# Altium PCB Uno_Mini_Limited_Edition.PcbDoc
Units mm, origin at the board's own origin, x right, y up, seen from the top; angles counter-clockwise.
Board outline 34.2 x 26.7 mm, 4 copper layers (TOP, SIG 1, PWR, BOTTOM), stack 1.586 mm thick; 63 components, 57 nets, 379 pads, 91 vias.
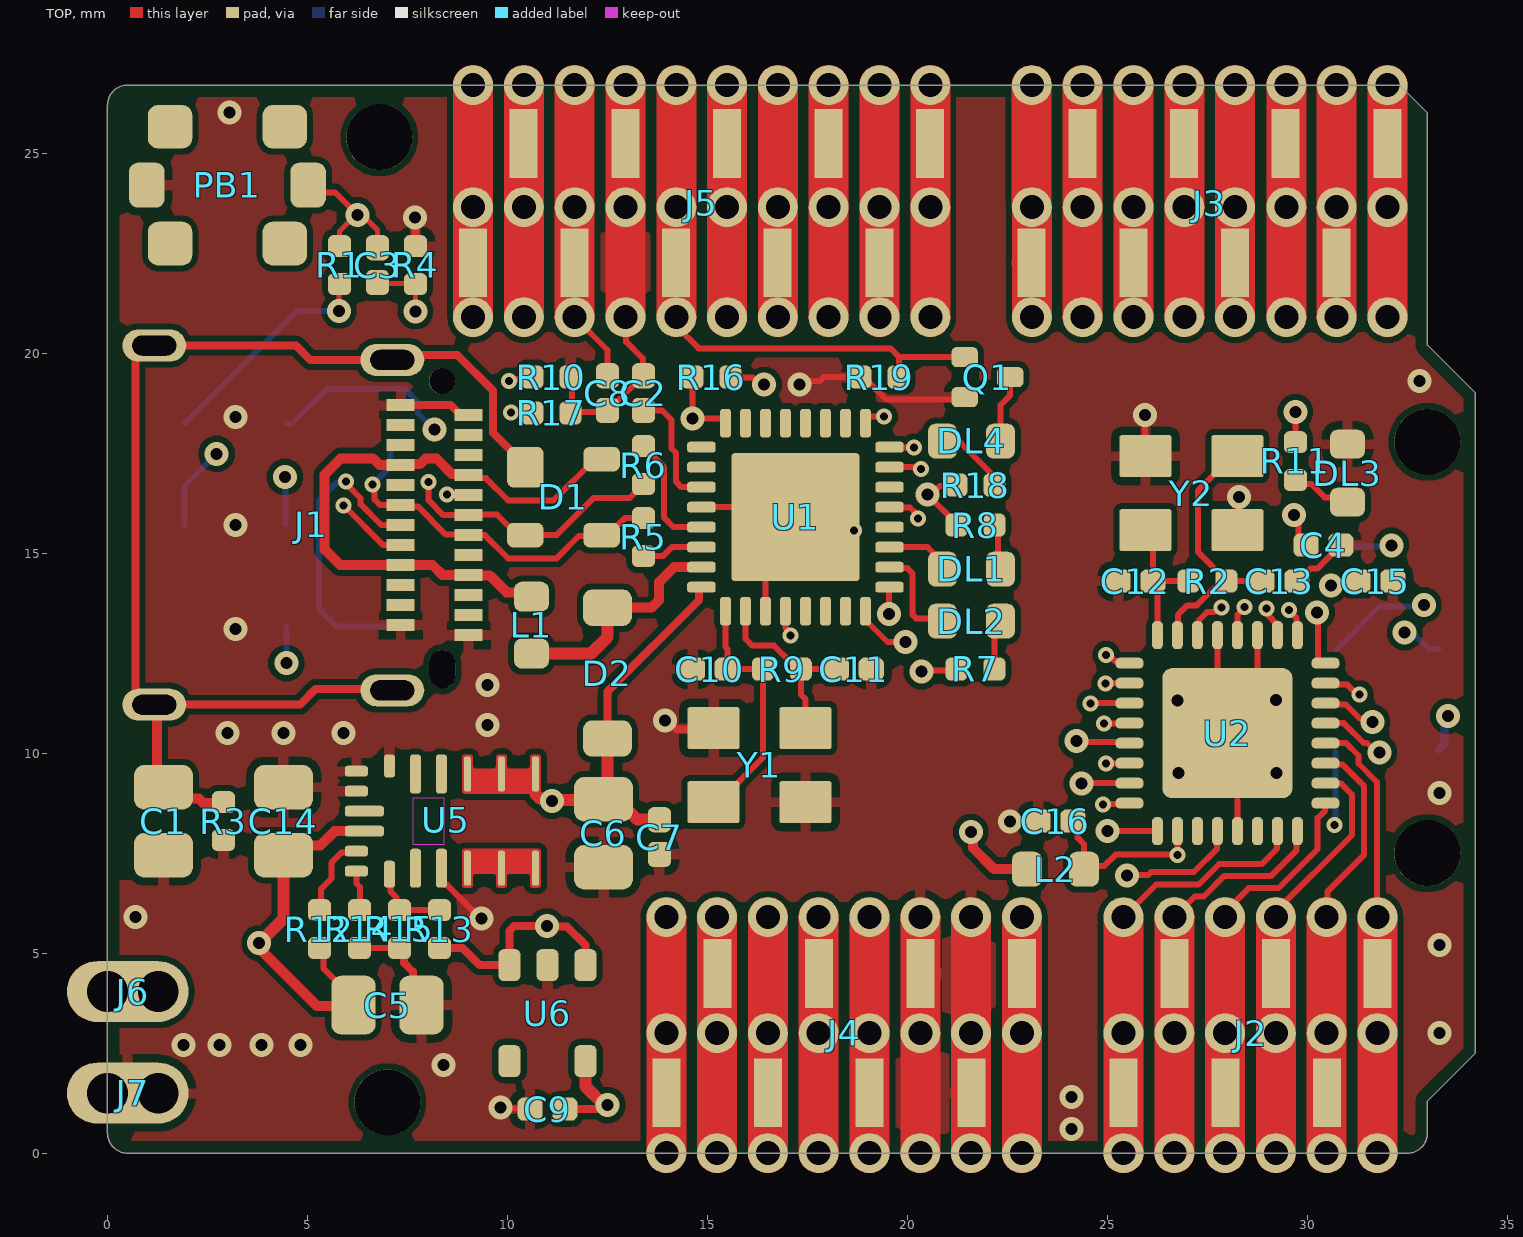
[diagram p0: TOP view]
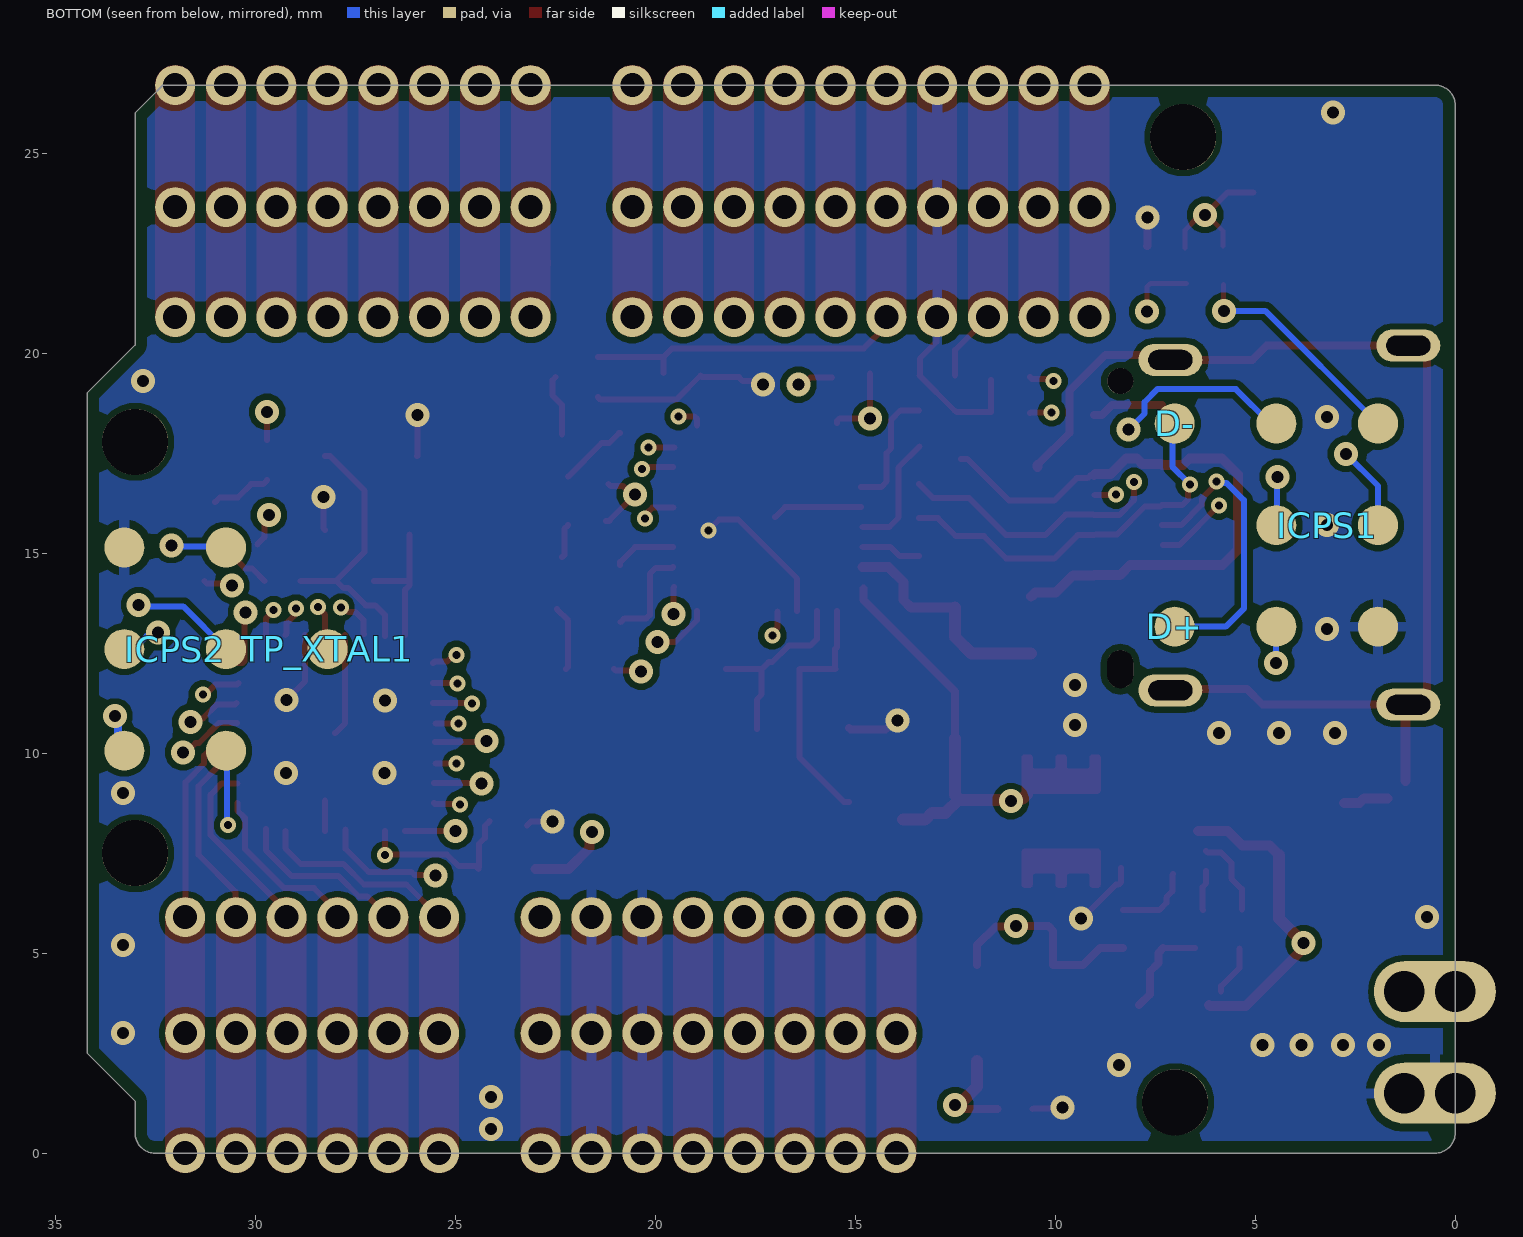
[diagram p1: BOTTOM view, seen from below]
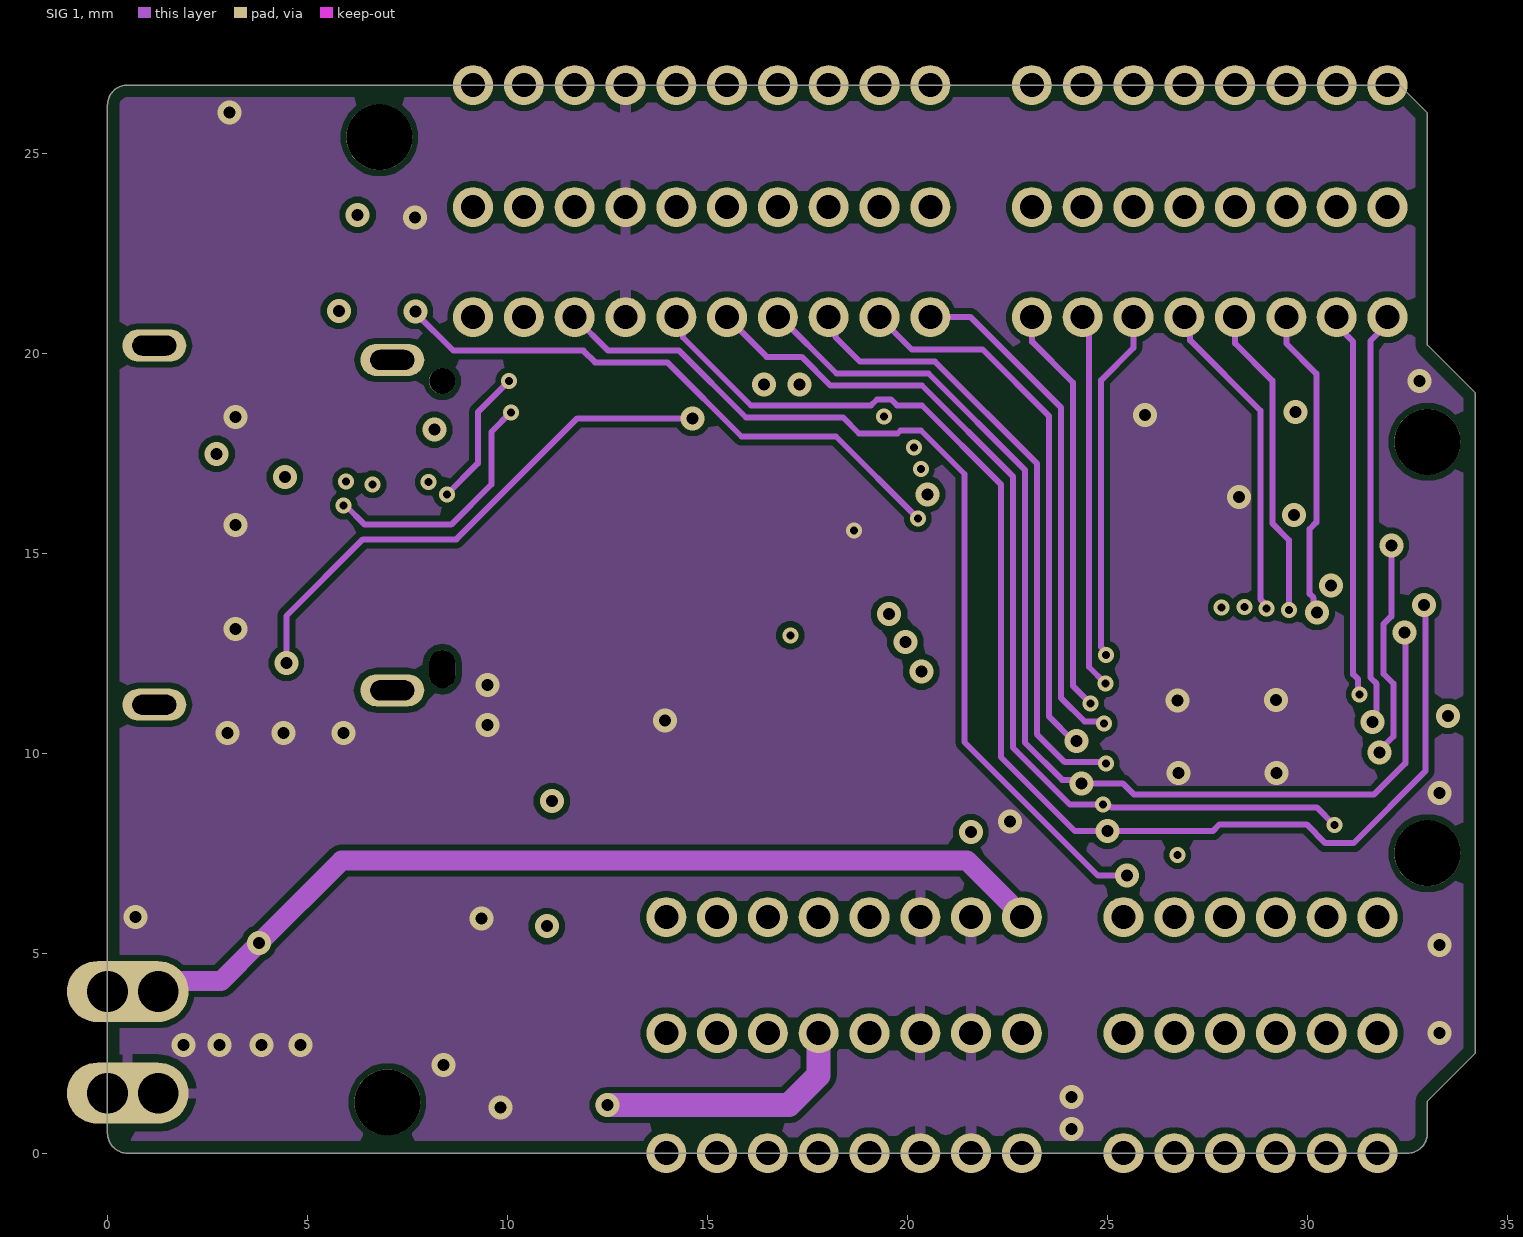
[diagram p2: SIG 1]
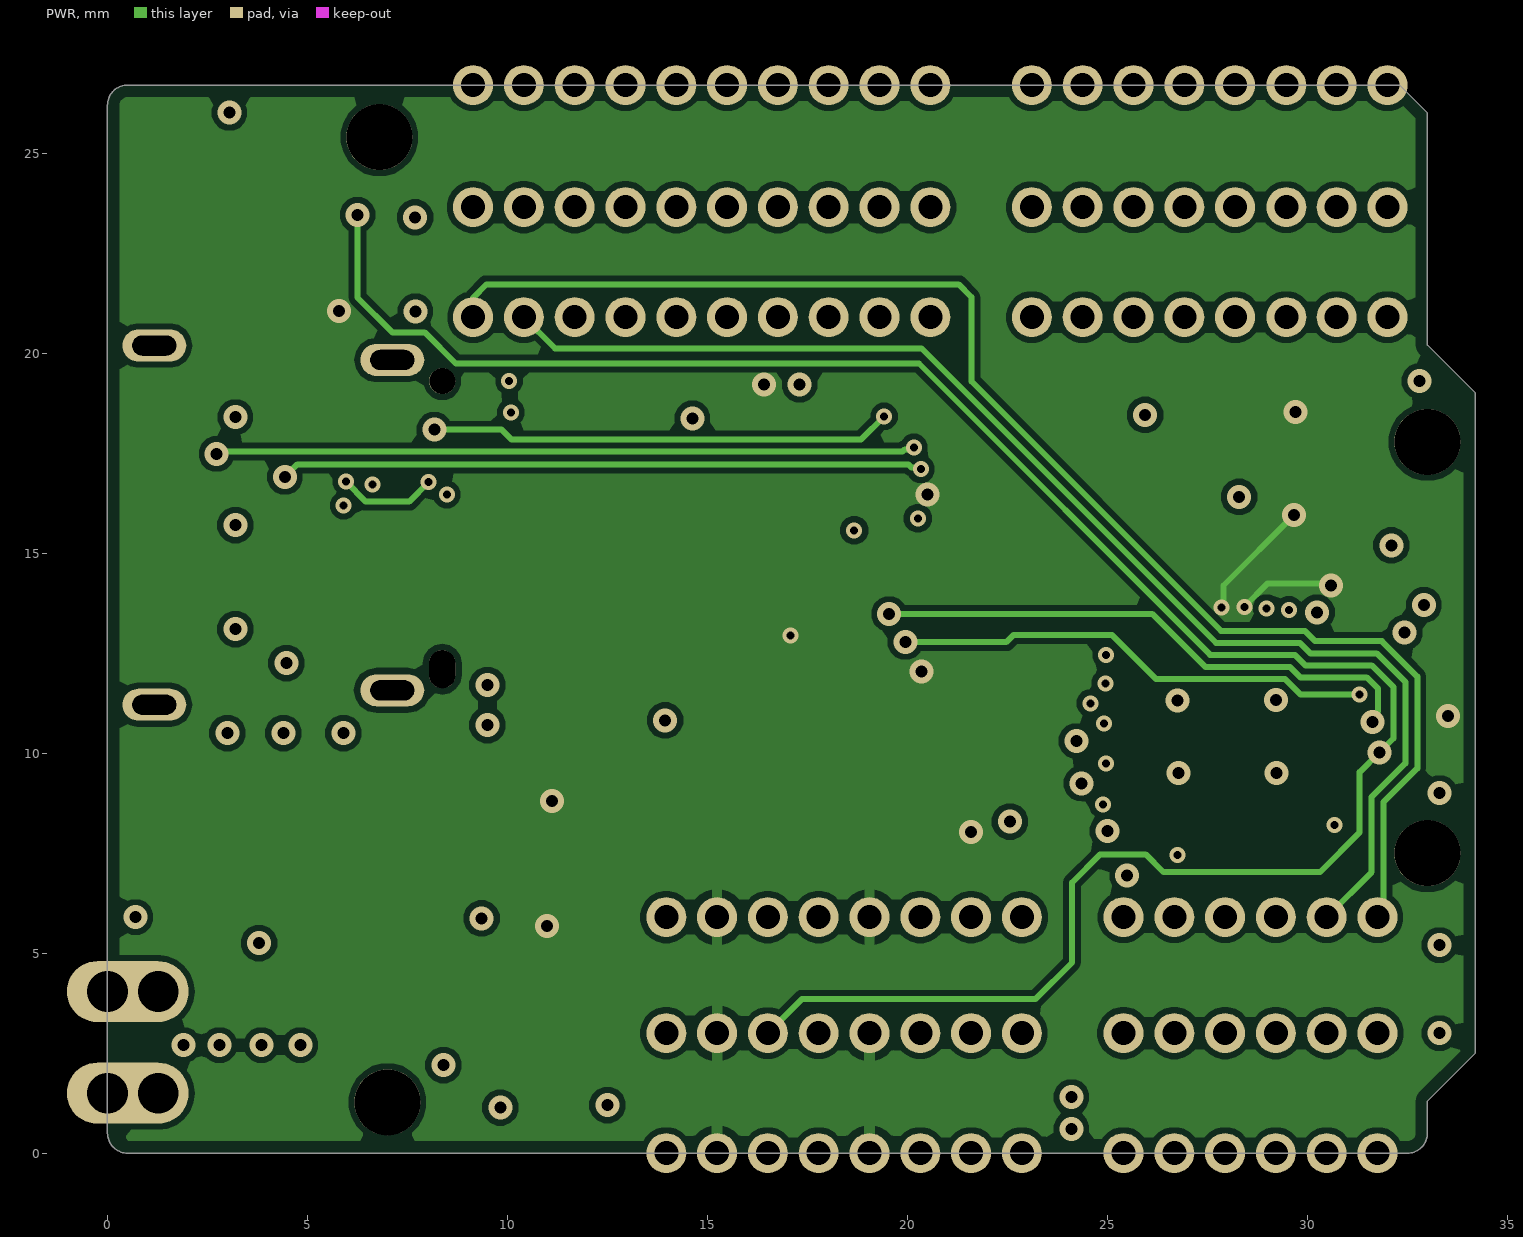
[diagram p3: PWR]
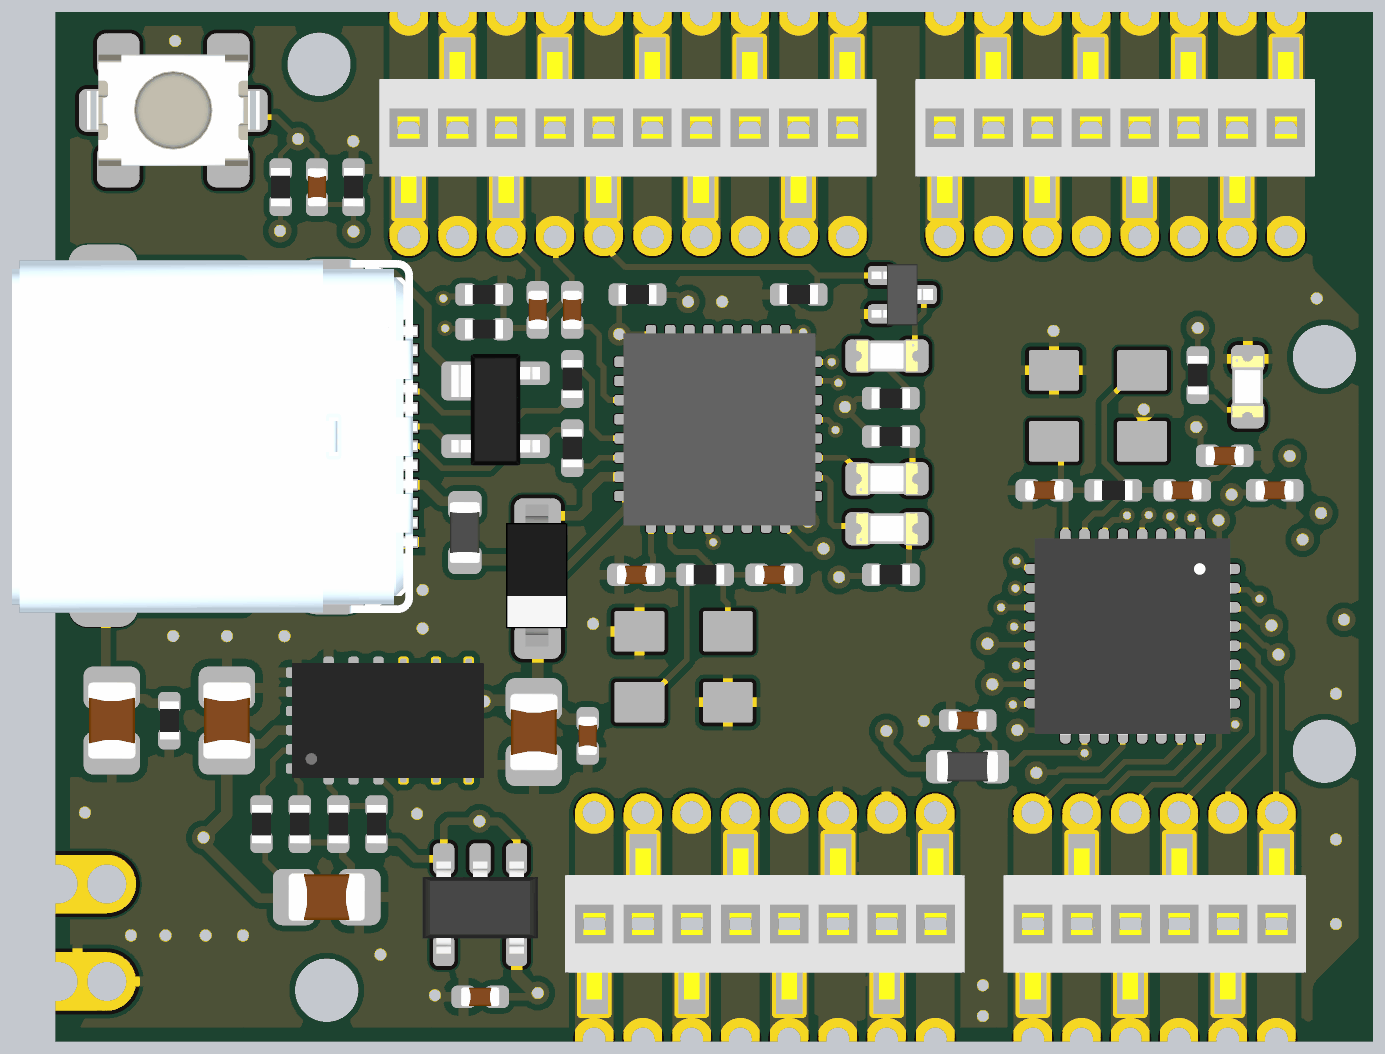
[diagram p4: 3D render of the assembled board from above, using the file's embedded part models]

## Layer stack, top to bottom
Top Solder: solder mask 0.0102, Solder Resist, Dk 3.5
TOP: signal copper 0.018
Dielectric1: prepreg 0.14, PP-014, Dk 4.2
SIG 1: signal copper 0.035
Dielectric2: core 1.2, FR-4, Dk 4.8
PWR: signal copper 0.035
Dielectric3: prepreg 0.14, PP-014, Dk 4.2
BOTTOM: signal copper 0.018
Bottom Solder: solder mask 0.0102, Solder Resist, Dk 3.5

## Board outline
0,0.5 0,26.2 cw(c0.5,26.2) 0.5,26.7 32.3,26.7 33,26 33,20.2 34.2,19 34.2,2.5 33,1.3 33,0.5 cw(c32.5,0.5) 32.5,0 0.5,0 cw(c0.5,0.5)

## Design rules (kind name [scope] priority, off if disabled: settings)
BoardOutlineClearance [All] p1: gap=0.3 ignorepadtopadclearanceinfootprint=FALSE
Clearance [All] p1: gap=0.15 ignorepadtopadclearanceinfootprint=TRUE
ComponentClearance [All] p1: gap=0.254 collisioncheckmode=3 verticalgap=-10 showdistances=FALSE
MinimumSolderMaskSliver [All] p1: minsoldermaskwidth=0.05
PlaneClearance [All] p1: clearance=0.3
PlaneConnect [All] p1: planeconnectstyle=Direct reliefexpansion=0.508 reliefentries=4 reliefconductorwidth=0.254 reliefairgap=0.254
PolygonConnect [All] p1: thpad.connectstyle=Relief thpad.reliefconductorwidth=0.254 thpad.reliefentries=4 thpad.polygonreliefangle="90 Angle" thpad.airgapwidth=0.2 smdpad.connectstyle=Relief smdpad.reliefconductorwidth=0.254 smdpad.reliefentries=4 smdpad.polygonreliefangle="90 Angle" smdpad.airgapwidth=0.2 via.connectstyle=Direct via.reliefconductorwidth=0.254 via.reliefentries=4 via.polygonreliefangle="90 Angle" via.airgapwidth=0.254
RoomDefinition Uno_Mini_LE [InComponentClass('Uno_Mini_LE')] p1: confinementstyle=ConfineIn formatcopy=TRUE lockcomponents=FALSE outline -25.5,-0.864 74.8,-0.864 74.8,44.5 -25.5,44.5
RoutingVias [All] p1: holewidth=0.2 width=0.4 viastyle="Through Hole" minholewidth=0.2 minwidth=0.4 maxholewidth=10 maxwidth=10
SilkToSilkClearance [All] p1: silktosilkclearance=0.05
SilkToSolderMaskClearance [IsPad] p1: minsilkscreentomaskgap=0.05 clearancetoexposedcopper=TRUE
SolderMaskExpansion [All] p1: expansion=0.102 istentingtop=FALSE
Width [All] p1: maxlimit=25.4 minlimit=0.127 preferedwidth=0.127 minimp=50.000000 maximp=50.000000 favimp=50.000000
24 further rules are at their usual default settings.

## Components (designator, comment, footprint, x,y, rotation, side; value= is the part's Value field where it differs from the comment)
C1 "C0805C472KDRACTU" CAP-0805 1.4,8.3 r90 top value=4.7nF
C2 "C0402C105K8PACTU" CAP-0402 13.4,19 r270 top value=1µF
C3 "C0402C104K4RACTU" CAP-0402 6.75,22.2 r90 top value=100nF
C4 "C0402C104K4RACTU" CAP-0402 30.4,15.2 r180 top value=100nF
C5 "GRM219R61C226ME15K" CAP-0805 7,3.7 r180 top value=22µF
C6 "GRM219R61C226ME15K" CAP-0805 12.4,8 r90 top value=22µF
C7 "C0402C104K4RACTU" CAP-0402 13.8,7.9 r90 top value=100nF
C8 "C0402C104K4RACTU" CAP-0402 12.5,19 r270 top value=100nF
C9 "C0402C105K8PACTU" CAP-0402 11,1.1 r0 top value=1µF
C10 "C0402H100J5GACTU" CAP-0402 15.06,12.1 r0 top value=10pF
C11 "C0402H100J5GACTU" CAP-0402 18.66,12.1 r180 top value=10pF
C12 "C0402H100J5GACTU" CAP-0402 25.7,14.3 r0 top value=10pF
C13 "C0402H100J5GACTU" CAP-0402 29.3,14.3 r180 top value=10pF
C14 "GRM219R61C226ME15K" CAP-0805 4.4,8.3 r270 top value=22µF
C15 "C0402C104K4RACTU" CAP-0402 31.7,14.3 r180 top value=100nF
C16 "C0402C104K4RACTU" CAP-0402 23.7,8.3 r0 top value=100nF
D1 "PRTR5V0U2X,215" SOT190P230X110-4N 11.4,16.4 r270 top
D2 "PMEG6020AELRX" SOD123-1 12.5,12 r90 top
D+ "CMP-018-0005-A.3" TP-1.00MM#1 7.2,13.64 r90 bottom
D- "CMP-018-0005-A.3" TP-1.00MM#2 7.01,17.74 r90 bottom
DL1 "KPT-1608SECK" LEDC1608X80N-AK 21.6,14.6 r0 top
DL2 "KPT-1608SECK" LEDC1608X80N-AK 21.6,13.3 r0 top
DL3 "HSMG-C190" LEDC1608X80N-AK 31,17 r270 top locked
DL4 "KPT-1608SECK" LEDC1608X80N-AK 21.6,17.8 r180 top
ICPS1 "PINHD-2X03-SM-TP" 2X03-TP 3.2,15.7 r270 bottom
ICPS2 "PINHD-2X03-SM-TP" 2X03-TP 32,12.6 r90 bottom locked
J1 "12401598E4#2A" 12401598E4#2A 5.1,15.7 r270 top locked
J2 "RMS-106-02-L-S" RMS-106-02-L-S-Footprint-1 28.58,3 r180 top
J3 "RSM-108-02-L-S" RMS-108-02-L-S-Footprint-1 27.55,23.75 r180 top
J4 "RSM-108-02-L-S" RMS-108-02-L-S-Footprint-1 18.42,3 r180 top
J5 "RSM-110-02-L-S" RMS-110-02-L-S-Footprint-1 14.85,23.75 r180 top
J6 "HEADER_2.54mm_CASTELLATED_1x1" PINHD-1X14_5VF 1.27,4.04 r90 top locked
J7 "HEADER_2.54mm_CASTELLATED_1x1" PINHD-1X14_5VF 1.27,1.5 r90 top locked
L1 "BLM18PG471SN1D" L-0603 10.6,13.2 r270 top
L2 "BLM18PG471SN1D" L-0603 23.7,7.1 r0 top
PB1 "PTS820J25KSMTRLFS" C&K_PTS820_NO_HOLES-1 3,24.2 r0 top locked
Q1 "2N7002T-7-F" SOT523 22,19.4 r270 top
R1 "CRCW040210K0FKED" RES-0402 5.8,22.2 r270 top value=10k
R2 "CRCW04021M00FKED" RES-0402 27.5,14.3 r180 top value=1M
R3 "CRCW04021M00FKED" RES-0402 2.9,8.3 r90 top value=1M
R4 "CRCW04021K00FKEDC" RES-0402 7.7,22.2 r90 top value=1k
R5 "CRCW040222R0JNEDC" RES-0402 13.4,15.4 r270 top value=22
R6 "CRCW040222R0JNEDC" RES-0402 13.4,17.2 r90 top value=22
R7 "CRCW0402330RJNED" RES-0402 21.7,12.1 r180 top value=330
R8 "CRCW0402330RJNED" RES-0402 21.7,15.7 r0 top value=330
R9 "CRCW04021M00FKED" RES-0402 16.86,12.1 r0 top value=1M
R10 "RC0402FR-075K1L" RES-0402 11.1,19.4 r180 top
R11 "CRCW0402330RJNED" RES-0402 29.7,17.3 r90 top value=330
R12 "CRCW0402100KFKEDC" RES-0402 5.3,5.6 r270 top value=100k
R13 "CRCW0402100KFKEDC" RES-0402 8.3,5.6 r270 top value=100k
R14 "CRCW040239K0FKED" RES-0402 6.3,5.6 r90 top value=39k
R15 "CRCW040219K1FKEDC" RES-0402 7.3,5.6 r90 top value=19.1k
R16 "CRCW040210K0FKED" RES-0402 15.1,19.4 r0 top locked value=10k
R17 "RC0402FR-075K1L" RES-0402 11.1,18.5 r0 top
R18 "CRCW0402330RJNED" RES-0402 21.7,16.7 r0 top value=330
R19 "CRCW04021M00FKED" RES-0402 19.3,19.4 r0 top value=1M
TP_XTAL1 "CMP-018-0005-A.3" TP-1.00MM#3 27.7,12.7 r90 bottom
U1 "ATMEGA16U2" ATMEL_QFN32 17.2,15.9 r90 top locked
U2 "ATMEGA328P-MUR" ATMEGA328P-MUR-Footprint-1 28,10.5 r270 top locked
U5 "MPM3610AGQV-P" POWER-LQFN20 8.6,8.3 r90 top
U6 "AP2112K-3.3TRG1" SOT25 11,3.5 r180 top
Y1 "CX3225SB16000D0GZJC1" CX3225SB16000D0GZJC1 16.3,9.7 r0 top
Y2 "CX3225SB16000D0GZJC1" CX3225SB16000D0GZJC1 27.1,16.5 r180 top

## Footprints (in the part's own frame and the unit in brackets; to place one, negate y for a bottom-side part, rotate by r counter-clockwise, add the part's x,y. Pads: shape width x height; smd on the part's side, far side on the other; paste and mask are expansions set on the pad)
2X03-TP [mm]
  rrect100% 1x1 smd paste+0: 1(-2.54,-1.27) 2(-2.54,1.27) 3(0,-1.27) 4(0,1.27) 5(2.54,-1.27) 6(2.54,1.27)
12401598E4#2A [mm]
  oval 1x1.8 on Top Paste: 0(-4.499,-3.932) 0(-4.131,2.023) 0(4.131,2.026) 0(4.461,-3.925)
  round 0.65 hole 0.65 unplated mask+0.05: 0(-3.6,3.27)
  oval 0.95x0.65 hole 0.65 slot 0.95 at 0 deg unplated mask+0: 0(3.6,3.27)
  rect 0.3x0.7 smd mask+0.04: A1(-2.75,3.93) A2(-2.25,3.93) A3(-1.75,3.93) A4(-1.25,3.93) A5(-0.75,3.93) A6(-0.25,3.93) A7(0.25,3.93) A8(0.75,3.93) A9(1.25,3.93) A10(1.75,3.93) B1(2.5,2.23) B2(2,2.23) B3(1.5,2.23) B4(1,2.23) B5(0.5,2.23) B6(0,2.23) B7(-0.5,2.23) B8(-1,2.23) B9(-1.5,2.23) B10(-2,2.23) B11(-2.5,2.23) B12(-3,2.23)
  rect 0.3x0.7 smd mask+0.03: A11(2.25,3.93) A12(2.75,3.93)
  oval 0.8x1.6 hole 0.5 slot 1.1 at 90 deg: "SHIELD 1"(-4.13,2.02) "SHIELD 2"(4.13,2.02) "SHIELD 3"(-4.49,-3.93) "SHIELD 4"(4.49,-3.93)
  body extent -4.6,-6.3 4.6,4.25, height 3.3
ATMEGA328P-MUR-Footprint-1 [mm]
  rrect80% 0.7x0.27 smd mask+0.03: 1(-2.45,1.75) 2(-2.45,1.25) 3(-2.45,0.75) 4(-2.45,0.25) 5(-2.45,-0.25) 6(-2.45,-0.75) 7(-2.45,-1.25) 8(-2.45,-1.75) 17(2.45,-1.75) 18(2.45,-1.25) 19(2.45,-0.75) 20(2.45,-0.25) 21(2.45,0.25) 22(2.45,0.75) 23(2.45,1.25) 24(2.45,1.75)
  rrect80% 0.27x0.7 smd mask+0.03: 9(-1.75,-2.45) 10(-1.25,-2.45) 11(-0.75,-2.45) 12(-0.25,-2.45) 13(0.25,-2.45) 14(0.75,-2.45) 15(1.25,-2.45) 16(1.75,-2.45) 25(1.75,2.45) 26(1.25,2.45) 27(0.75,2.45) 28(0.25,2.45) 29(-0.25,2.45) 30(-0.75,2.45) 31(-1.25,2.45) 32(-1.75,2.45)
  rrect15% 3.254x3.254 smd paste-5 mask+0.05: 33(0,0)
  body extent -2.56,-2.56 2.56,2.56, height 1.01
ATMEL_QFN32 [mm]
  rrect50% 0.711x0.27 smd mask+0.03: 1(-2.351,1.75) 2(-2.351,1.25) 3(-2.351,0.75) 4(-2.351,0.25) 5(-2.351,-0.25) 6(-2.351,-0.75) 7(-2.351,-1.25) 8(-2.351,-1.75) 17(2.351,-1.75) 18(2.351,-1.25) 19(2.351,-0.75) 20(2.351,-0.25) 21(2.351,0.25) 22(2.351,0.75) 23(2.351,1.25) 24(2.351,1.75)
  rrect50% 0.27x0.711 smd mask+0.03: 9(-1.75,-2.351) 10(-1.25,-2.351) 11(-0.75,-2.351) 12(-0.25,-2.351) 13(0.25,-2.351) 14(0.75,-2.351) 15(1.25,-2.351) 16(1.75,-2.351) 25(1.75,2.351) 26(1.25,2.351) 27(0.75,2.351) 28(0.25,2.351) 29(-0.25,2.351) 30(-0.75,2.351) 31(-1.25,2.351) 32(-1.75,2.351)
  rrect5% 3.2x3.2 smd paste-3.302 mask+0.05: EXP(0,0)
  body extent -2.51,-2.54 2.49,2.46, height 0.85
C&K_PTS820_NO_HOLES-1 [mm]
  rrect49% 0.89x1.12 smd: 5(-2.015,0) 6(2.015,0)
  rrect46% 1.11x1.09 smd: PAD(-1.434,-1.46) PAD(-1.434,1.46) PAD(1.434,-1.46) PAD(1.434,1.46)
  body extent -2.25,-1.45 2.25,1.45, height 2
CAP-0402 [mm] "Chip Capacitor, 2-Leads, Body  0402 (in) 1005 (mm), IPC Medium Density"
  rrect52% 0.63x0.58 smd mask+0: 1(-0.435,0) 2(0.435,0)
  body extent -0.5,-0.25 0.5,0.25, height 0.5
CAP-0805 [mm] "Chip Capacitor, Body 0805 imperial, 2.0x1.2mm, IPC Medium Density"
  rrect45% 1.11x1.47 smd mask+0: 1(-0.85,0) 2(0.85,0)
  body extent -1,-0.62 1,0.63, height 1.25
CX3225SB16000D0GZJC1 [mm]
  rrect10% 1.3x1.05 smd: 1(-1.15,-0.925) 2(1.15,-0.925) 3(1.15,0.925) 4(-1.15,0.925)
  body extent -1.59,-1.21 1.59,1.21, height 0.6
L-0603 [mm] "Chip Inductor - Body 0603 imperial,1.6x0.8mm, IPC High Density"
  rrect51% 0.75x0.87 smd mask+0: 1(-0.71,0) 2(0.71,0)
  body extent -0.8,-0.4 0.8,0.4, height 0.8
LEDC1608X80N-AK [mm]
  rrect50% 0.72x0.87 smd: A(0.725,0) C(-0.725,0)
  body extent -0.8,-0.4 0.8,0.4, height 0.79
PINHD-1X14_5VF [mil]
  round 27.56 hole 40 mask+7.87: 1(0,50)
  oval 60x120 hole 40 copper offset 0,30 paste-100: 1(0,0)
POWER-LQFN20 [mm]
  rrect52% 0.675x0.27 smd paste+0 mask+0: 1(-1.328,1.55)
  rrect52% 0.975x0.27 smd paste+0 mask+0: 2(-1.178,0.9) 3(-1.178,0.25) 10(1.178,0.25) 11(1.178,0.9)
  rrect52% 0.875x0.17 smd paste+0 mask+0: 4(-1.178,-0.4) 5(-1.178,-1.25) 6(-1.178,-2.1) 7(1.178,-2.1) 8(1.178,-1.25) 9(1.178,-0.4)
  rrect52% 0.575x0.27 smd paste+0 mask+0: 12(1.378,1.55)
  rrect52% 0.27x0.575 smd paste+0 mask+0: 13(1.25,2.378) 14(0.75,2.378) 17(-0.75,2.378) 18(-1.25,2.378)
  rrect52% 0.27x0.975 smd paste+0 mask+0: 15(0.25,2.178) 16(-0.25,2.178)
  TOP region: 0.69,-2.165 0.695,-2.192 0.711,-2.214 0.733,-2.23 0.76,-2.235 0.76,-2.235 1.595,-2.235 1.622,-2.23 1.644,-2.214 1.66,-2.192 1.665,-2.165 1.665,-2.165 1.665,-2.035 1.66,-2.008 1.644,-1.986 1.622,-1.97 1.595,-1.965 1.595,-1.965 1.38,-1.965 1.353,-1.96 1.331,-1.944 1.315,-1.922 1.31,-1.895 1.31,-1.895 1.31,-1.455 1.31,-1.455 1.315,-1.428 1.33,-1.406 1.353,-1.39 1.38,-1.385 1.38,-1.385 1.595,-1.385 1.622,-1.38 1.644,-1.364 1.66,-1.342 1.665,-1.315 1.665,-1.315 1.665,-1.185 1.665,-1.185 1.66,-1.158 1.645,-1.136 1.622,-1.12 1.595,-1.115 1.595,-1.115 1.38,-1.115 1.353,-1.11 1.331,-1.094 1.315,-1.072 1.31,-1.045 1.31,-1.045 1.31,-1.045 1.31,-0.605 1.315,-0.578 1.331,-0.556 1.353,-0.54 1.38,-0.535 1.38,-0.535 1.595,-0.535 1.595,-0.535 1.622,-0.53 1.645,-0.514 1.66,-0.492 1.665,-0.465 1.665,-0.465 1.665,-0.465 1.665,-0.335 1.66,-0.308 1.644,-0.286 1.622,-0.27 1.595,-0.265 1.595,-0.265 0.76,-0.265 0.733,-0.27 0.711,-0.286 0.695,-0.308 0.69,-0.335 0.69,-0.335
  TOP region: -1.665,-2.165 -1.66,-2.192 -1.644,-2.214 -1.622,-2.23 -1.595,-2.235 -1.595,-2.235 -0.76,-2.235 -0.733,-2.23 -0.711,-2.214 -0.695,-2.192 -0.69,-2.165 -0.69,-2.165 -0.69,-2.165 -0.69,-0.335 -0.695,-0.308 -0.711,-0.286 -0.733,-0.27 -0.76,-0.265 -0.76,-0.265 -1.595,-0.265 -1.622,-0.27 -1.645,-0.286 -1.66,-0.308 -1.665,-0.335 -1.665,-0.335 -1.665,-0.335 -1.665,-0.465 -1.66,-0.492 -1.644,-0.514 -1.622,-0.53 -1.595,-0.535 -1.595,-0.535 -1.38,-0.535 -1.353,-0.54 -1.331,-0.556 -1.315,-0.578 -1.31,-0.605 -1.31,-0.605 -1.31,-1.045 -1.31,-1.045 -1.315,-1.072 -1.33,-1.094 -1.353,-1.11 -1.38,-1.115 -1.38,-1.115 -1.595,-1.115 -1.622,-1.12 -1.644,-1.136 -1.66,-1.158 -1.665,-1.185 -1.665,-1.185 -1.665,-1.315 -1.665,-1.315 -1.66,-1.342 -1.645,-1.364 -1.622,-1.38 -1.595,-1.385 -1.595,-1.385 -1.38,-1.385 -1.353,-1.39 -1.331,-1.406 -1.315,-1.428 -1.31,-1.455 -1.31,-1.455 -1.31,-1.455 -1.31,-1.895 -1.31,-1.895 -1.315,-1.922 -1.331,-1.944 -1.353,-1.96 -1.38,-1.965 -1.38,-1.965 -1.595,-1.965 -1.595,-1.965 -1.622,-1.97 -1.644,-1.985 -1.66,-2.008 -1.665,-2.035 -1.665,-2.035
  TOP keep-out region: -0.575,0.18 0.575,0.18 0.575,0.97 -0.575,0.97
  body extent -1.5,-2.5 1.5,2.5, height 1.6
RES-0402 [mm] "Chip Resistor, 2-Leads, Body  0402 (in) 1005 (mm), IPC Medium Density"
  rrect51% 0.55x0.58 smd mask+0: 1(-0.475,0) 2(0.475,0)
  body extent -0.5,-0.25 0.5,0.25, height 0.34
RMS-106-02-L-S-Footprint-1 [mm]
  rect 0.7x1.715 smd: 1(-3.175,-1.492) 2(-1.905,1.492) 3(-0.635,-1.492) 4(0.635,1.492) 5(1.905,-1.492) 6(3.175,1.492)
  body extent -3.94,-1.97 3.94,1.97, height 6.09
RMS-108-02-L-S-Footprint-1 [mm]
  rect 0.7x1.715 smd: 1(-4.445,-1.492) 2(-3.175,1.492) 3(-1.905,-1.492) 4(-0.635,1.492) 5(0.635,-1.492) 6(1.905,1.492) 7(3.175,-1.492) 8(4.445,1.492)
  body extent -5.21,-1.97 5.21,1.97, height 6.02
RMS-110-02-L-S-Footprint-1 [mm]
  rect 0.7x1.715 smd: 1(-5.715,-1.492) 2(-4.445,1.492) 3(-3.175,-1.492) 4(-1.905,1.492) 5(-0.635,-1.492) 6(0.635,1.492) 7(1.905,-1.492) 8(3.175,1.492) 10(5.715,1.492)
  rect 0.7x1.715 smd mask+0.12: 9(4.445,-1.492)
  body extent -6.48,-1.97 6.48,1.97, height 6.11
SOD123-1 [mm]
  rrect50% 0.91x1.22 smd: A(1.635,0) C(-1.635,0)
  body extent -1.78,-0.78 1.92,0.82, height 1.27
SOT25 [mil]
  rrect50% 21.65x31.5 smd: 1(-37.4,-47.24) 2(0,-47.24) 3(37.4,-47.24) 4(37.4,47.24) 5(-37.4,47.24)
  body extent -59,-44 59,50, height 43
SOT190P230X110-4N [mm]
  rrect33% 1.01x0.91 smd paste+0 mask+0: 1(-0.75,-0.955)
  rrect49% 0.61x0.91 smd paste+0 mask+0: 2(0.95,-0.955) 3(0.95,0.955) 4(-0.95,0.955)
  body extent -1.45,-1.15 1.45,1.15, height 1
SOT523 [mm]
  rrect50% 0.5x0.66 smd: D(0,0.57) G(-0.5,-0.57) S(0.5,-0.57)
  body extent -0.8,-0.8 0.8,0.8, height 0.8
TP-1.00MM#1 [mm]
  rrect100% 1x1 smd paste-2.54: X(-0.48,-0.19)
TP-1.00MM#2 [mm]
  rrect100% 1x1 smd paste-2.54: X(0.5,0)
TP-1.00MM#3 [mm]
  rrect100% 1x1 smd paste-2.54: X(-0.1,0.49)

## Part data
C1: library part C0059-A.9, "CAP CHIP 0805 4.7nF 1000V X7R 10%", Case Code (Imperial)=0805, Case Code (Metric)=2012, Dielectric=X7R, Manufacturer=KEMET, Tolerance=10%, Voltage=1kV
C2 C9: library part C0017-A.9, "CAP CHIP 0402 1uF 10V X5R 10%", Case Code (Imperial)=0402, Case Code (Metric)=1005, Dielectric=X5R, Manufacturer=KEMET, Manufacturer 2=AVX, Manufacturer Part Number 2=GRM155R61A105KE15D, Tolerance=10%, Voltage=10V
C3 C4 C7 C8 C15 C16: library part C0012-A.9, "CAP CHIP 0402 100nF 16V X7R 10%", Case Code (Imperial)=0402, Case Code (Metric)=1005, Dielectric=X7R, Manufacturer=KEMET, Manufacturer 2=AVX, Manufacturer Part Number 2=0402YC104KAT2A, Tolerance=10%, Voltage=16V
C5 C6 C14: library part C0058-A.9, "CAP CHIP 0805 22uF 16V X5R 20%", Case Code (Imperial)=0805, Case Code (Metric)=2012, Dielectric=X5R, Manufacturer=Murata, Manufacturer 2=Samsung, Manufacturer Part Number 2=CL21A226MAQNNNE, Tolerance=20%, Voltage=16V
C10 C11 C12 C13: library part C0006-A.9, "CAP CHIP 0402 10pF 50V C0G 5%", Case Code (Imperial)=0402, Case Code (Metric)=1005, Dielectric=C0G, Manufacturer=KEMET, Manufacturer 2=AVX, Manufacturer Part Number 2=04025A100KAT2A, Tolerance=5%, Voltage=50V
D1: library part D0025-A.3, "TVS ARRAY 4LIN.8kV 1pF SOT143B", Manufacturer=Nexperia
D2: library part D0026-A.2, "DIODE SCHOTTKY SMD 1A 40V SOD123FL", Manufacturer=Nexperia
D+ D- TP_XTAL1: library part UT0013-A.2, "Test point 1.00mm"
DL1 DL2 DL4: library part L0006-A.4, "LED SMD 0603 ORANGE601 250mcd 120^", Manufacturer=Kingbright
DL3: library part L0009-A.4, "LED SMD 0603 GREEN/568 15mcd 120^", Manufacturer=Broadcom
ICPS1 ICPS2: library part J0066-A.3, "2X03 6 TEST POINTS"
J1: library part J0220-A.5, "CONN RCP USB3.1 TYPEC 24P SMD RA", Flammability Rating="UL94 V-0", Manufacturer="Amphenol ICC (Commercial Products)"
J2: library part J0193-A.5, "CONN PIN HEADER FEMALE SMD 1X6", Manufacturer=SAMTEC
J3 J4: library part J0194-A.7, "CONN PIN HEADER FEMALE SMD 1X8", Contact Resistance=10mR, Insulation Color=Black, Manufacturer=SAMTEC, Max Operating Temperature=125°C, Min Operating Temperature=-55°C
J5: library part J0196-A.5, "CONN PIN HEADER FEMALE SMD 1X10", Manufacturer=SAMTEC
J6 J7: library part J0207-A.4, "CONN THD HEADER 2.54mm CASTELLATED 1x1"
L1 L2: library part I0006-A.3, "FERRITE SMD 0603 470R 1A 0.2R", Case Code (Imperial)=0603, Case Code (Metric)=1608, Current=1A, DC Resistance (DCR)=200mR, Manufacturer=Murata, Max Operating Temperature=125°C, Min Operating Temperature=-55°C, Package Quantity=1, Test Frequency=100MHz, Tolerance=25%
PB1: library part B0006-A.7, "PUSHBUTTON SMD PTS820 NO HOLES", Color=Black, Manufacturer=C&K, Max Operating Temperature=85°C, Min Operating Temperature=-40°C
Q1: library part T0003-A.2, "MOSFET N-CH 60V 115mA SOT523", Manufacturer="Diodes Inc."
R1 R16: library part R0003-A.5, "RES CHIP 0402 10K 1% 1/16W", Case Code (Imperial)=0402, Case Code (Metric)=1005, Manufacturer=Vishay, Manufacturer 2=Panasonic, Manufacturer Part Number 2=ERJ-2RKF1002X, Power=63mW, Tolerance=1%
R2 R3 R9 R19: library part R0058-A.5, "RES CHIP 0402 1M 1% 1/16W", Case Code (Imperial)=0402, Case Code (Metric)=1005, Manufacturer=Vishay, Manufacturer 2=Panasonic, Manufacturer Part Number 2=ERJ-2RKF1004X, Power=63mW, Tolerance=1%
R4: library part R0007-A.5, "RES CHIP 0402 1K 1% 1/16W", Case Code (Imperial)=0402, Case Code (Metric)=1005, Manufacturer=Vishay, Manufacturer 2=Panasonic, Manufacturer Part Number 2=ERJ-2RKF1001X, Power=63mW, Tolerance=1%
R5 R6: library part R0010-A.5, "RES CHIP 0402 22R 5% 1/16W", Case Code (Imperial)=0402, Case Code (Metric)=1005, Manufacturer=Vishay, Manufacturer 2=Panasonic, Manufacturer Part Number 2=ERJ-2GEJ220X, Power=63mW, Tolerance=5%
R7 R8 R11 R18: library part R0017-A.5, "RES CHIP 0402 330R 5% 1/16W", Case Code (Imperial)=0402, Case Code (Metric)=1005, Manufacturer=Vishay, Manufacturer 2=Panasonic, Manufacturer Part Number 2=ERJ-2GEJ331X, Power=63mW, Tolerance=5%
R10 R17: library part R0210-A.6, "RES CHIP 0402 5K1 1% 1/16W", Case/Package=0402, Manufacturer=YAGEO, Tolerance=1%
R12 R13: library part R0001-A.5, "RES CHIP 0402 100K 1% 1/16W", Case Code (Imperial)=0402, Case Code (Metric)=1005, Manufacturer=Vishay, Manufacturer 2=Panasonic, Manufacturer Part Number 2=ERJ-2RKF1003X, Power=63mW, Tolerance=1%
R14: library part R0036-A.7, "RES CHIP 0402 39K 1% 1/16W", Case Code (Imperial)=0402, Case Code (Metric)=1005, Manufacturer=Vishay, Manufacturer 2=Panasonic, Manufacturer Part Number 2=ERJ-2RKF3902X, Power=63mW, Tolerance=1%
R15: library part R0033-A.5, "RES CHIP 0402 19k1 1% 1/16W", Case Code (Imperial)=0402, Case Code (Metric)=1005, Manufacturer=Vishay, Manufacturer 2=Panasonic, Manufacturer Part Number 2=ERJ-2RKF1912X, Power=63mW, Tolerance=1%
U1: library part U0035-A.7, "IC ATMEGA16U2", Manufacturer=Microchip
U2: library part U0037-A.7, "IC MICROCONTROLLER 8 bit", Case/Package=VQFN, Frequency=20MHz, Manufacturer=Microchip, Max Operating Temperature=125°C, Min Operating Temperature=-40°C
U5: library part U0075-A.8, "IC StpDwn-CONV.21V 1.2A", Case/Package=QFN, Manufacturer=MPS, Max Input Voltage=21V, Max Operating Temperature=125°C, Max Output Current=1.2A, Min Input Voltage=4.5V, Min Operating Temperature=-40°C, Operating Supply Current=200uA, Output Voltage=5.5V, Package Quantity=500, Switching Frequency=2MHz, Voltage - Output 1=18.48V
U6: library part U0027-A.6, "IC V-REG LDO 3V3 600mA +En  SOT25", Manufacturer="Diodes Inc"
Y1 Y2: library part X0019-A.4, "CRYSTAL 16.0000MHZ 8PF SMD", Manufacturer="Kyocera International Inc. Electronic Components"

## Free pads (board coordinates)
  round 1.651 hole 1.651 unplated mask+0: 0(6.8,25.4) 0(7,1.27) 0(33,7.5) 0(33,17.78)
  round 1 hole 0.6 mask+0.05: 2(9.14,20.9) 2(9.14,23.65) 2(9.14,26.7) 2(10.41,20.9) 2(10.41,23.65) 2(10.41,26.7) 2(11.68,20.9) 2(11.68,23.65) 2(11.68,26.7) 2(12.95,20.9) 2(12.95,23.65) 2(12.95,26.7) 2(13.97,0) 2(13.97,3) 2(13.97,5.9) 2(14.22,20.9) 2(14.22,23.65) 2(14.22,26.7) 2(15.24,0) 2(15.24,3) 2(15.24,5.9) 2(15.49,20.9) 2(15.49,23.65) 2(15.49,26.7) 2(16.51,0) 2(16.51,3) 2(16.51,5.9) 2(16.76,20.9) 2(16.76,23.65) 2(16.76,26.7) 2(17.78,0) 2(17.78,3) 2(17.78,5.9) 2(18.03,20.9) 2(18.03,23.65) 2(18.03,26.7) 2(19.05,0) 2(19.05,3) 2(19.05,5.9) 2(19.3,20.9) 2(19.3,23.65) 2(19.3,26.7) 2(20.32,0) 2(20.32,3) 2(20.32,5.9) 2(20.57,20.9) 2(20.57,23.65) 2(20.57,26.7) 2(21.59,0) 2(21.59,3) 2(21.59,5.9) 2(22.86,0) 2(22.86,3) 2(22.86,5.9) 2(23.11,20.9) 2(23.11,23.65) 2(23.11,26.7) 2(24.38,20.9) 2(24.38,23.65) 2(24.38,26.7) 2(25.4,0) 2(25.4,3) 2(25.4,5.9) 2(25.65,20.9) 2(25.65,23.65) 2(25.65,26.7) 2(26.67,0) 2(26.67,3) 2(26.67,5.9) 2(26.92,20.9) 2(26.92,23.65) 2(26.92,26.7) 2(27.94,0) 2(27.94,3) 2(27.94,5.9) 2(28.19,20.9) 2(28.19,23.65) 2(28.19,26.7) 2(29.21,0) 2(29.21,3) 2(29.21,5.9) 2(29.47,20.9) 2(29.47,23.65) 2(29.47,26.7) 2(30.48,0) 2(30.48,3) 2(30.48,5.9) 2(30.73,20.9) 2(30.73,23.65) 2(30.73,26.7) 2(31.75,0) 2(31.75,3) 2(31.75,5.9) 2(32,20.9) 2(32,23.65) 2(32,26.7)

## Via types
v1: diameter 0.6, hole 0.3, TOP to BOTTOM, tented both sides, 61 vias
v2: diameter 0.4, hole 0.2, TOP to BOTTOM, tented both sides, 26 vias
v3: diameter 0.6/0.6/0.6/0.6 (per signal layer), hole 0.3, TOP to BOTTOM, tented both sides, 4 vias

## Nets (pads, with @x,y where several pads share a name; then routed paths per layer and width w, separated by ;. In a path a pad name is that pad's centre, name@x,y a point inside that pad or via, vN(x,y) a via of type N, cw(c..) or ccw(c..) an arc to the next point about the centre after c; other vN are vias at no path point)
+3.3V: C9.2 J4.5 pad.2@17.78,0 pad.2@17.78,3 pad.2@17.78,5.9 U6.5 | length 14.9
  TOP w0.127: v1@12.318,1.2 12.416,1.2 v1(12.5,1.2)
  TOP w0.2: C9.2 12.223,1.1 12.318,1.195 v1@12.318,1.2
  TOP w0.3: U6.5 11.95,1.666 v1@12.416,1.2
  TOP w1: pad.2@17.78,0 17.78,3 pad.2@17.78,5.9
  SIG 1 w0.6: v1(12.5,1.2) 17.033,1.2 17.78,1.947 pad.2@17.78,3
+5V: C4.2 C6.2 C7.2 C15.2 D2.C ICPS1.2 ICPS2.2 J4.4 J4.7 L2.1 pad.2@15.24,0 pad.2@15.24,3 pad.2@15.24,5.9 pad.2@19.05,0 pad.2@19.05,3 pad.2@19.05,5.9 R1.2 R7.2 R8.1 R11.2 R13.2 R16.2 R18.1 U1.4 U1.32 U2.4 U2.6 U5.7 U5.8 U5.9 U6.1 U6.3 | length 49.6
  TOP w0.127: v1@5.792,21.067 R1.2@5.792,21.717 ; U5.7 10.703,9.476 10.703,8.968 ; C6.2 C6.2@12.5,8.95
  TOP w0.15: R16.2@15.584,19.391 16.12,19.391 16.296,19.215 v1(16.418,19.215) ; U1.4@16.946,13.546 16.946,13.139 17.072,13.013 v2(17.072,12.946) ; v1(20.351,12.037) 20.382,12.069 20.994,12.069 R7.2@21.025,12.1 ; R18.1@21.17,16.733 21.118,16.68 20.813,16.68 20.605,16.472 v1(20.506,16.472) 20.506,16.453 21.141,15.819 21.141,15.8 R8.1@21.225,15.8 ; U2.6@27.275,12.975 27.29,12.99 27.29,13.326 27.488,13.525 27.668,13.525 27.787,13.644 v2(27.855,13.644) ; U2.4@28.252,12.952 28.252,13.456 28.425,13.629 v2(28.425,13.656) ; v1(29.659,15.949) 29.659,15.827 29.772,15.714 29.772,15.393 C4.2@29.946,15.219 ; R11.2@29.7,17.83 v1@29.7,18.531 ; v1(30.582,14.188) 30.638,14.244 31.209,14.244 C15.2
  TOP w0.2: R13.2 8.875,5.125 9.3,4.7 U6.3 10.05,5.558 10.167,5.676 v1(10.982,5.676) 10.99,5.668 11.482,5.668 11.95,5.2 U6.1 ; D2.C 12.5,11.538 14.794,13.832 U1.32@14.794,14.115
  TOP w0.25: U5.7@10.695,9.483 U5.7 ; v1(21.583,8.03) 21.639,7.974 21.639,7.632 22.171,7.1 L2.1
  TOP w0.3: 10.703,8.968 10.811,8.86 11.05,8.86 v1(11.107,8.803) 11.131,8.826 12.376,8.826 C6.2 12.743,8.507 13.082,8.507 13.25,8.338 13.797,8.338 C7.2 ; C6.2@12.5,8.95 D2.C
  TOP w1: pad.2@15.24,0 15.24,3 pad.2@15.24,5.9 ; pad.2@19.05,0 19.05,3 pad.2@19.05,5.9
  PWR w0.15: v2(27.855,13.644) 27.9,13.689 27.9,14.19 v1(29.659,15.949) ; v2(28.425,13.656) 28.425,13.666 28.998,14.239 30.532,14.239 v1(30.582,14.188)
  BOTTOM w0.15: ICPS1.2 4.749,21.059 v1(5.784,21.059)
  BOTTOM w0.2: ICPS2.2@33.286,10.09 33.423,10.227 33.423,10.689 33.432,10.697 33.432,10.852 v1(33.508,10.928)
  other v1: 29.699,18.532
A0: J2.6 pad.2@25.4,0 pad.2@25.4,3 pad.2@25.4,5.9 U2.23 | length 10.7
  TOP w0.15: pad.2@25.4,5.9 26.216,6.716 27.279,6.716 27.789,7.226 28.853,7.226 29.243,7.617 U2.23@29.243,8.049
  TOP w1: pad.2@25.4,0 J2.6@25.4,1.508 ; pad.2@25.4,5.734 25.4,3 25.4,1.513 J2.6
A1: J2.5 pad.2@26.67,0 pad.2@26.67,3 pad.2@26.67,5.9 U2.24 | length 10.2
  TOP w0.15: pad.2@26.67,5.9 27.186,6.416 27.403,6.416 27.912,6.925 29.081,6.925 29.73,7.574 U2.24@29.73,8.109
  TOP w1: pad.2@26.67,0 26.67,3 26.67,4.492 pad.2@26.67,5.9
A2: J2.4 pad.2@27.94,0 pad.2@27.94,3 pad.2@27.94,5.9 U2.25 | length 10.1
  TOP w0.15: pad.2@27.94,6.036 28.529,6.625 29.275,6.625 30.25,7.601 30.25,8.374 30.44,8.564 U2.25@30.44,8.75
  TOP w1: pad.2@27.94,0 27.94,3 pad.2@27.94,5.9
A3: J2.3 pad.2@29.21,0 pad.2@29.21,3 pad.2@29.21,5.9 U2.26 | length 10.5
  TOP w0.15: pad.2@29.21,5.9 29.21,6.048 31.114,7.951 31.114,8.964 30.834,9.244 U2.26@30.437,9.244
  TOP w1: pad.2@29.21,0 29.21,3 pad.2@29.21,5.9
A4/SDA: J2.2 J5.9 pad.2@10.41,20.9 pad.2@10.41,23.65 pad.2@10.41,26.7 pad.2@30.48,0 pad.2@30.48,3 pad.2@30.48,5.9 U2.27 | length 49
  TOP w0.15: U2.27@30.459,9.759 30.508,9.71 30.881,9.71 31.415,9.177 31.415,7.456 30.496,6.537 pad.2@30.496,5.916
  TOP w1: pad.2@10.41,20.9 10.41,23.65 pad.2@10.41,26.7 ; pad.2@30.48,0 30.48,1.508 30.48,3 pad.2@30.48,5.9
  PWR w0.15: pad.2@10.41,20.9 11.193,20.117 20.356,20.117 27.714,12.758 29.808,12.758 30.07,12.497 31.73,12.497 32.445,11.781 32.445,9.745 31.606,8.906 31.606,7.026 pad.2@30.5,5.92
A5/SCL: J2.1 J5.10 pad.2@9.14,20.9 pad.2@9.14,23.65 pad.2@9.14,26.7 pad.2@31.75,0 pad.2@31.75,3 pad.2@31.75,5.9 U2.28 | length 52.8
  TOP w0.15: U2.28@30.445,10.256 30.96,10.256 31.275,9.941 31.275,9.741 31.74,9.276 pad.2@31.74,5.91
  TOP w1: pad.2@9.14,20.9 9.14,23.65 pad.2@9.14,26.7 ; pad.2@31.749,0 J2.1@31.749,4.492 ; pad.2@31.75,5.9 31.75,4.497 J2.1
  PWR w0.15: pad.2@9.14,20.9 9.14,21.385 9.475,21.72 21.28,21.72 21.6,21.4 21.6,19.297 27.839,13.058 29.933,13.058 30.191,12.8 31.859,12.8 32.745,11.914 32.745,9.621 31.906,8.782 31.906,6.116 pad.2@31.7,5.91
AREF: C8.1 J5.8 pad.2@11.68,20.9 pad.2@11.68,23.65 pad.2@11.68,26.7 U2.20 | length 34.2
  TOP w0.15: pad.2@11.68,20.9 12.5,20.08 C8.1 ; v1(25.491,6.937) 25.506,6.952 26.016,6.952 26.091,7.027 27.162,7.027 27.742,7.607 U2.20@27.742,8.092
  TOP w1: pad.2@11.68,20.9 11.68,23.65 pad.2@11.68,26.7
  SIG 1 w0.15: pad.2@11.7,20.9 11.7,20.88 12.512,20.069 14.286,20.069 15.964,18.39 18.391,18.39 18.789,17.992 19.751,17.992 19.825,18.066 20.337,18.066 21.425,16.979 21.425,10.275 24.763,6.937 v1(25.491,6.937)
D+: D1.2 D+.X J1.A6 J1.B6 R6.1 | length 16.7
  TOP w0.127: J1.A6 J1.A6@9.043,15.963
  TOP w0.15: v2(5.966,16.794) 5.966,16.731 6.33,16.367 6.33,16.22 6.85,15.7 J1.B6 ; v2(8.03,16.779) 8.03,16.318 8.398,15.95 J1.A6 ; J1.A6@9.043,15.963 9.737,15.963 10.25,15.45 D1.2 11.224,15.45 12.149,16.375 13.05,16.375 R6.1
  PWR w0.15: v2(5.966,16.794) 5.966,16.781 6.457,16.289 7.54,16.289 v2(8.03,16.779)
  BOTTOM w0.15: v2(5.966,16.794) 5.924,16.752 5.71,16.752 5.283,16.325 5.283,13.612 5.735,13.16 D+.X
D-: D1.3 D-.X J1.A7 J1.B7 R5.1 | length 9.3
  TOP w0.15: v2(6.63,16.718) 6.677,16.67 6.677,16.345 6.822,16.2 J1.B7 7.361,16.169 7.755,16.169 8.46,15.464 J1.A7@8.982,15.464 ; J1.A7@9.023,15.449 9.436,15.449 10.013,14.871 11.228,14.871 11.784,15.428 12.487,15.428 12.934,15.875 R5.1
  BOTTOM w0.15: v2(6.63,16.718) 6.63,16.722 7.072,17.164 D-.X@7.072,17.781
DTR: C3.1 R4.1 U1.13 | length 17.2
  TOP w0.127: C3.1@6.72,21.745 R4.1@7.6,21.745 ; R4.1@7.621,21.746 7.699,21.667 v1@7.699,21.045
  TOP w0.15: U1.13@19.54,16.14 20.064,16.14 20.211,15.993 20.211,15.919 v2(20.259,15.871)
  SIG 1 w0.15: v1(7.699,21.045) 7.699,21.013 8.65,20.061 11.899,20.061 12.192,19.769 13.998,19.769 15.851,17.916 18.213,17.916 v2(20.259,15.871)
GND: C1.1 C2.1 C4.1 C5.1 C6.1 C7.1 C8.2 C9.1 C10.1 C11.1 C12.1 C13.1 C14.1 C15.1 C16.1 DL3.C ICPS1.6 ICPS2.6 J1.A1 J1.A12 J1.B1 J1.B12 J4.2 J4.3 J5.7 J7.1 pad.2@12.95,20.9 pad.2@12.95,23.65 pad.2@12.95,26.7 pad.2@20.32,0 pad.2@20.32,3 pad.2@20.32,5.9 pad.2@21.59,0 pad.2@21.59,3 pad.2@21.59,5.9 PB1.5 Q1.S R3.1 R4.2 R10.1 R14.1 R15.1 R17.2 R19.1 U1.3 U1.28 U1.EXP U2.3 U2.5 U2.21 U2.33 U5.3 U5.12 U5.13 U5.14 U6.2 Y1.2 Y1.4 Y2.2 Y2.4 | length 50.5
  TOP w0.127: pad.2@12.95,20.9 pad.2@12.967,20.883
  TOP w0.15: R14.1@6.5,5.125 R15.1 ; U5.3 8.35,6.77 8.41,6.71 8.483,6.71 9.322,5.871 v1(9.353,5.871) ; v1(9.82,1.14) 9.84,1.12 10.545,1.12 C9.1 ; R10.1@11.608,19.333 11.608,18.533 C8.2@12.468,18.533 ; C8.2@12.515,18.565 C2.1@13.385,19.435 ; pad.2@12.967,20.883 12.967,20.284 13.385,19.866 C2.1@13.385,19.45 ; U1.28 16.75,16.15 U1.EXP@17,15.9 ; U1.3 16.45,14.365 17.926,15.84 18.4,15.84 v2(18.669,15.571) ; v1(17.306,19.215) 17.392,19.301 17.806,19.301 17.906,19.401 R19.1@18.824,19.401 ; R19.1@18.866,19.442 19.47,18.838 21.368,18.838 Q1.S ; v1(22.562,8.287) 22.568,8.294 23.101,8.294 C16.1@23.198,8.196 ; v1(25.942,18.454) 25.942,17.433 Y2.2 ; U2.5 27.75,10.75 U2.33 ; U2.21 28.25,8.819 ; Y2.4 28.293,15.618 v1(28.293,16.406) ; U2.3 28.75,11.801 v3(29.218,11.333) ; C13.1@29.76,14.3 30.08,14.62 30.255,14.62 C4.1
  TOP w0.2: R15.1 7.419,5.006 7.419,4.75 7.634,4.535 7.634,3.966 C5.1@7.9,3.7 ; J1.B12 8.58,18.7 8.83,18.45 J1.A1 ; v1(7.692,23.396) 7.696,23.392 7.696,22.679 R4.2 ; v1(13.942,10.822) 14.009,10.822 14.244,10.587 15.112,10.587 Y1.4
  TOP w1: pad.2@12.95,20.9 12.95,23.65 pad.2@12.95,26.7 ; pad.2@20.32,0 20.32,3 pad.2@20.32,5.9 ; pad.2@21.59,0 21.59,3 pad.2@21.59,5.9
  other v1: 24.1,0.6 24.1,1.4 8.4,2.2 1.9,2.7 2.8,2.7 3.846,2.7 4.82,2.7 33.3,3 33.3,5.2 0.7,5.9 33.3,9 3,10.5 4.4,10.5 5.9,10.5 9.5,10.7 9.5,11.7 3.2,13.1 3.2,15.7 3.2,18.4 32.8,19.3 3.05,26.01
  other v3: 26.772,9.504 29.225,9.504 26.757,11.31
IO0: J3.1 pad.2@32,20.9 pad.2@32,23.65 pad.2@32,26.7 U1.9 U2.30 | length 32.2
  TOP w0.15: U1.9@19.529,14.15 19.544,14.135 v1(19.544,13.479) ; U2.30@30.468,11.251 30.509,11.21 30.962,11.21 31.307,10.866 31.534,10.866 v1(31.62,10.78)
  TOP w0.254: pad.2@31.931,20.831 pad.2@32,20.9
  TOP w1: pad.2@32,20.9 32,23.65 pad.2@32,26.7
  SIG 1 w0.15: v1(31.62,10.78) 31.62,10.902 31.73,11.012 31.73,11.731 31.57,11.891 31.57,20.304 32,20.734 pad.2@32,20.9
  PWR w0.15: v1(19.544,13.479) 19.549,13.484 26.119,13.484 27.445,12.158 29.56,12.158 29.821,11.897 31.481,11.897 31.76,11.618 31.76,11.041 31.62,10.902 v1(31.62,10.78)
IO1: J3.2 pad.2@30.73,20.9 pad.2@30.73,23.65 pad.2@30.73,26.7 U1.8 U2.31 | length 30
  TOP w0.15: U1.8 18.95,13.329 19.501,12.777 19.944,12.777 v1(19.946,12.78) ; U2.31@30.414,11.752 30.455,11.71 30.999,11.71 31.237,11.472 v2(31.305,11.472)
  TOP w1: pad.2@30.73,20.9 30.73,23.65 pad.2@30.73,26.7
  SIG 1 w0.15: pad.2@30.73,20.9 30.73,20.699 31.142,20.287 31.142,11.972 31.257,11.857 31.257,11.52 v2(31.305,11.472)
  PWR w0.15: v1(19.946,12.78) 19.953,12.773 22.467,12.773 22.645,12.951 25.119,12.951 26.211,11.858 29.436,11.858 29.574,11.72 29.594,11.7 29.822,11.472 v2(31.305,11.472)
IO2: J3.3 pad.2@29.47,20.9 pad.2@29.47,23.65 pad.2@29.47,26.7 U2.32 | length 15.1
  TOP w0.15: v1(30.24,13.52) 30.262,13.498 30.262,12.308 30.319,12.25 U2.32
  TOP w1: pad.2@29.47,20.9 29.47,23.65 pad.2@29.47,26.7
  SIG 1 w0.15: pad.2@29.47,20.9 29.47,20.24 30.224,19.486 30.224,15.772 30.055,15.602 30.055,13.983 30.154,13.884 30.154,13.606 v1(30.24,13.52)
IO3: J3.4 pad.2@28.19,20.9 pad.2@28.19,23.65 pad.2@28.19,26.7 U2.1 | length 14.4
  TOP w0.15: v2(29.535,13.581) 29.535,13.56 29.728,13.368 29.728,12.972 U2.1@29.738,12.962
  TOP w1: pad.2@28.19,20.9 28.19,23.65 pad.2@28.19,26.7
  SIG 1 w0.15: pad.2@28.19,20.9 28.19,20.24 29.12,19.31 29.12,15.745 29.535,15.33 v2(29.535,13.581)
IO4: J3.5 pad.2@26.92,20.9 pad.2@26.92,23.65 pad.2@26.92,26.7 U2.2 | length 14.7
  TOP w0.15: v2(28.98,13.62) 29.028,13.572 29.028,13.434 29.21,13.252 29.21,12.99 U2.2@29.242,12.958
  TOP w1: pad.2@26.92,20.9 26.92,23.65 pad.2@26.92,26.7
  SIG 1 w0.15: pad.2@26.901,20.926 27.066,20.761 27.066,20.321 28.82,18.567 28.82,13.848 28.98,13.688 v2(28.98,13.62)
IO5: J3.6 pad.2@25.65,20.9 pad.2@25.65,23.65 pad.2@25.65,26.7 U2.9 | length 15.3
  TOP w0.15: v2(24.969,12.459) 25.033,12.459 25.202,12.29 25.51,12.29 U2.9
  TOP w1: pad.2@25.65,20.9 25.65,23.65 pad.2@25.65,26.7
  SIG 1 w0.15: v2(24.969,12.459) 24.969,12.527 24.843,12.653 24.843,19.326 25.65,20.133 pad.2@25.65,20.9
IO6: J3.7 pad.2@24.38,20.9 pad.2@24.38,23.65 pad.2@24.38,26.7 U2.10 | length 15.8
  TOP w0.15: v2(24.946,11.747) 24.948,11.748 25.548,11.748 U2.10
  TOP w1: pad.2@24.38,20.9 24.38,23.65 24.38,23.7 pad.2@24.38,26.7
  SIG 1 w0.15: pad.2@24.38,20.9 24.539,20.741 24.539,12.154 v2(24.946,11.747)
IO7: J3.8 pad.2@23.11,20.9 pad.2@23.11,23.65 pad.2@23.11,26.7 U2.11 | length 17
  TOP w0.15: v2(24.573,11.247) 24.575,11.248 25.548,11.248 U2.11@25.551,11.252
  TOP w1: pad.2@23.102,26.692 23.102,23.708 23.11,23.7 23.11,23.65 J3.8@23.11,22.258 ; J3.8 23.11,22.253 pad.2@23.11,20.9
  SIG 1 w0.15: pad.2@23.116,20.894 23.116,20.284 24.135,19.265 24.135,11.681 24.57,11.247 v2(24.573,11.247)
IO8: J5.1 pad.2@20.57,20.9 pad.2@20.57,23.65 pad.2@20.57,26.7 U2.12 | length 19.2
  TOP w0.15: v2@24.915,10.747 U2.12@25.492,10.747
  TOP w1: pad.2@20.57,20.9 20.57,23.65 pad.2@20.57,26.7
  SIG 1 w0.15: pad.2@20.57,20.9 21.582,20.9 23.835,18.647 23.835,11.384 24.427,10.793 24.864,10.793 v2(24.912,10.745)
IO9: J5.2 pad.2@19.3,20.9 pad.2@19.3,23.65 pad.2@19.3,26.7 U2.13 | length 20.8
  TOP w0.15: v1(24.221,10.302) 24.247,10.276 25.501,10.276 U2.13@25.505,10.273
  TOP w1: pad.2@19.3,20.9 19.3,23.65 pad.2@19.3,26.7
  SIG 1 w0.15: pad.2@19.3,20.9 20.108,20.092 21.878,20.092 23.535,18.435 23.535,10.918 24.152,10.302 v1(24.221,10.302)
MISO_1: ICPS2.1 J5.5 pad.2@15.49,20.9 pad.2@15.49,23.65 pad.2@15.49,26.7 U2.16 | length 32.7
  TOP w0.15: v2(24.883,8.714) 24.901,8.732 25.506,8.732 U2.16@25.533,8.759
  TOP w1: pad.2@15.49,20.9 15.49,23.65 pad.2@15.49,26.7
  SIG 1 w0.15: pad.2@15.49,20.9 16.48,19.91 17.353,19.91 18.071,19.192 20.362,19.192 22.635,16.919 22.635,10.142 24.064,8.713 v2@24.882,8.713 ; v2(24.883,8.714) 24.931,8.666 25.074,8.666 25.096,8.645 30.229,8.645 v2(30.675,8.198)
  BOTTOM w0.15: v2@30.703,8.225 ICPS2.1@30.703,10.033
MISO_2: ICPS1.1 U1.17 | length 16.9
  TOP w0.15: U1.17@18.951,18.194 18.951,18.358 19.01,18.417 v2(19.415,18.417)
  PWR w0.15: v1(8.171,18.086) 9.856,18.086 10.097,17.845 18.843,17.845 v2(19.415,18.417)
  BOTTOM w0.15: ICPS1.1 4.621,18.24 5.481,19.1 7.445,19.1 7.765,18.78 7.765,18.492 v1(8.171,18.086)
MOSI_1: ICPS2.4 J5.4 pad.2@16.76,20.9 pad.2@16.76,23.65 pad.2@16.76,26.7 U2.15 | length 36.3
  TOP w0.15: v1(24.346,9.246) 24.348,9.248 25.531,9.248 U2.15@25.534,9.251
  TOP w1: pad.2@16.76,20.9 16.76,23.65 pad.2@16.76,26.7
  SIG 1 w0.15: pad.2@16.76,20.9 16.817,20.9 18.225,19.492 20.527,19.492 22.935,17.084 22.935,10.266 23.87,9.332 24.346,9.332 v1(24.346,9.246) 25.381,9.246 25.665,8.961 31.659,8.961 32.445,9.747 32.445,13.002 v1(32.432,13.015)
  BOTTOM w0.15: v1(32.432,13.015) 32.518,12.929 32.711,12.929 33.04,12.6 ICPS2.4
MOSI_2: ICPS1.4 U1.16 | length 20.3
  TOP w0.15: U1.16@19.521,17.644 19.522,17.646 20.157,17.646 v2(20.161,17.641)
  PWR w0.15: v1(2.731,17.483) 2.779,17.531 2.937,17.531 2.944,17.537 19.877,17.537 19.934,17.594 20.114,17.594 v2(20.161,17.641)
  BOTTOM w0.15: ICPS1.4 1.93,16.682 v1(2.731,17.483)
NC: J4.8 pad.2@13.97,0 pad.2@13.97,3 pad.2@13.97,5.9 | length 5.9
  TOP w1: pad.2@13.97,0 13.97,3 pad.2@13.97,5.9
NetC1_2: "J1.SHIELD 1" "J1.SHIELD 2" "J1.SHIELD 3" "J1.SHIELD 4" C1.2 D1.1 R3.2 | length 28.7
  TOP w0.127: 1.17,11.21 1.242,11.138 ; R3.2@2.777,8.752 R3.2@2.8,8.775 ; 7.09,11.6 7.12,11.57
  TOP w0.2: 0.7,11.521 0.7,19.879 ; 1.17,11.21 4.81,11.21 5.2,11.6 7.09,11.6 ; 1.17,20.19 4.71,20.19 5.07,19.83 7.12,19.83 ; 7.244,19.954 8.746,19.954 9.637,19.063 9.637,18.008 D1.1@10.445,17.2
  TOP w0.25: C1.2@1.242,9.308 1.242,11.138 ; C1.2@1.687,8.863 2.282,8.863 2.394,8.752 R3.2@2.777,8.752 ; D1.1 D1.1@10.445,17.2
NetC2_2: C2.2 U1.27 | length 3.1
  TOP w0.15: C2.2 13.868,18.565 14.1,18.333 14.1,17.616 14.215,17.501 14.215,16.785 14.348,16.652 U1.27@14.848,16.652
NetC10_2: C10.2 R9.1 U1.1 Y1.1 | length 6.3
  TOP w0.15: Y1.1 15.275,8.775 15.736,9.237 16.385,9.885 R9.1 C10.2 15.5,12.105 15.5,12.6 15.45,12.65 U1.1
NetC11_2: C11.2 R9.2 U1.2 Y1.3 | length 4.8
  TOP w0.15: U1.2 15.95,12.858 16.119,12.689 16.664,12.689 17.078,12.275 17.16,12.275 R9.2 ; Y1.3@17.453,10.609 17.453,11.347 17.335,11.465 R9.2 ; C11.2 R9.2
NetC12_2: C12.2 R2.2 U2.8 Y2.3 | length 3.4
  TOP w0.15: Y2.3@26.135,15.46 C12.2 ; U2.8 26.25,14.085 26.135,14.2 C12.2 ; R2.2 C12.2
NetC13_2: C13.2 R2.1 U2.7 Y2.1 | length 6.9
  TOP w0.15: U2.7@26.759,12.934 26.759,13.459 26.997,13.697 27.235,13.697 27.664,14.125 27.791,14.125 R2.1@27.971,14.304 ; R2.1 27.975,14.315 27.26,15.03 27.26,16.56 28.125,17.425 Y2.1 ; R2.1@27.98,14.304 C13.2@28.861,14.304
NetC16_2: C16.2 L2.2 U2.18 | length 4.3
  TOP w0.15: C16.2 24.252,8.183 24.252,7.883 24.408,7.727 L2.2@24.408,7.159 ; L2.2 24.492,7.182 24.922,7.182 25.204,7.463 26.739,7.463 v2(26.749,7.452) ; v2(26.749,7.452) U2.18
NetDL1_A: DL1.A R8.2 | length 0.9
  TOP w0.15: R8.2 22.268,15.607 22.268,14.952 22.32,14.9 DL1.A@22.325,14.9
NetDL1_C: DL1.C U1.11 | length 1.6
  TOP w0.15: U1.11 20.502,15.15 20.875,14.777 DL1.C@20.875,14.7
NetDL2_A: DL2.A R7.1 | length 1.6
  TOP w0.15: R7.1@22.23,12.1 22.175,12.155 22.175,13.318 DL2.A@22.457,13.6
NetDL2_C: DL2.C U1.10 | length 2.5
  TOP w0.15: U1.10 19.575,14.626 19.996,14.626 20.131,14.49 20.131,13.457 20.219,13.369 20.771,13.369 DL2.C@20.864,13.276
NetDL3_A: DL3.A R11.1 | length 1.5
  TOP w0.15: R11.1 29.801,16.724 30.101,16.724 30.428,16.397 30.878,16.397 DL3.A
NetDL4_A: DL4.A R18.2 | length 1.8
  TOP w0.15: DL4.A@20.875,18 20.904,18 21.152,17.752 21.335,17.752 R18.2@22.175,16.912
NetDL4_C: DL4.C Q1.D | length 1.6
  TOP w0.15: DL4.C@22.325,17.96 22.325,18.7 22.561,18.935 22.561,19.329 Q1.D@22.49,19.4
NetICPS1_5: ICPS1.5 R16.1 U1.24 | length 16.3
  TOP w0.15: R16.1@14.625,19.489 v1(14.625,18.37) 15.39,18.37 15.45,18.31 U1.24
  SIG 1 w0.15: v1(4.475,12.249) 4.475,13.432 6.386,15.344 8.723,15.344 11.748,18.37 v1(14.625,18.37)
  BOTTOM w0.15: v1@4.472,12.251 ICPS1.5@4.472,13.158
NetJ1_A5: J1.A5 R10.2 | length 4.7
  TOP w0.127: v2(8.484,16.466) v2@8.492,16.458 ; J1.A5@9.022,16.458 J1.A5
  TOP w0.15: v2@8.492,16.458 J1.A5@9.022,16.458 ; v2(10.038,19.301) 10.086,19.349 10.574,19.349 R10.2
  SIG 1 w0.15: v2(8.484,16.466) 9.261,17.243 9.261,18.524 10.03,19.293 v2@10.03,19.301
NetJ1_B5: J1.B5 R17.1 | length 8.7
  TOP w0.15: v2(5.905,16.191) 6.896,15.2 J1.B5@7.3,15.2 ; v2(10.087,18.521) 10.097,18.51 10.615,18.51 R17.1
  SIG 1 w0.15: v2(5.905,16.191) 5.951,16.191 6.43,15.712 8.592,15.712 9.6,16.72 9.6,18.034 v2(10.087,18.521)
NetR5_2: R5.2 U1.30 | length 1.5
  TOP w0.15: R5.2 13.887,14.925 14.111,15.15 U1.30@14.815,15.15
NetR6_2: R6.2 U1.29 | length 3
  TOP w0.15: R6.2@13.395,17.663 13.915,17.143 13.915,16.439 13.915,15.885 14.147,15.653 U1.29@14.821,15.653
NetR12_1: R12.1 U5.17 | length 2
  TOP w0.15: R12.1@5.334,6.096 5.334,6.601 5.595,6.862 5.595,7.257 5.855,7.518 6.19,7.518 U5.17
NetR13_1: R13.1 R15.2 U5.1 | length 1.9
  TOP w0.15: U5.1 7.071,6.951 7.071,6.547 7.222,6.396 7.222,6.253 7.4,6.075 R13.1
NetR14_2: R14.2 U5.18 | length 1
  TOP w0.15: U5.18 6.223,6.745 6.315,6.653 6.315,6.09 R14.2
RESET: C3.2 ICPS2.5 J4.6 pad.2@16.51,0 pad.2@16.51,3 pad.2@16.51,5.9 PB1.6 R1.1 U2.29 | length 72.4
  TOP w0.127: R1.1 5.8,23.048 6.208,23.456 v1(6.252,23.456) 6.304,23.403 6.426,23.403 6.75,23.08 C3.2
  TOP w0.15: PB1.6@5.035,24.02 5.687,24.02 v1(6.252,23.456) ; U2.29@30.452,10.748 30.91,10.748 31.403,10.255 31.487,10.255 31.722,10.02 v1(31.8,10.02)
  TOP w1: pad.2@16.51,0 16.51,3 pad.2@16.51,5.9
  SIG 1 w0.15: v1(31.8,10.02) 31.8,10.072 32.145,10.417 32.145,11.741 31.907,11.979 31.907,13.232 32.095,13.421 v1(32.095,15.196)
  PWR w0.15: v1(6.252,23.456) 6.252,21.388 7.12,20.52 7.928,20.52 8.708,19.74 20.288,19.74 27.57,12.458 29.684,12.458 29.946,12.197 31.605,12.197 32.145,11.657 32.145,10.365 v1(31.8,10.02) 31.306,9.526 31.306,8.018 30.315,7.027 26.396,7.027 25.954,7.469 24.817,7.469 24.113,6.764 24.113,4.762 23.205,3.855 17.365,3.855 pad.2@16.51,3
  BOTTOM w0.15: ICPS2.5@30.738,15.132 30.774,15.168 32.067,15.168 v1(32.095,15.196)
SCLK_1: ICPS2.3 J5.6 pad.2@14.22,20.9 pad.2@14.22,23.65 pad.2@14.22,26.7 Q1.G R19.2 U2.17 | length 51.4
  TOP w0.15: pad.2@14.22,20.9 14.22,20.68 14.781,20.119 19.575,20.119 19.794,19.9 ; R19.2@19.786,19.5 19.786,19.9 19.794,19.9 ; 19.817,19.877 19.794,19.9 ; Q1.G 19.794,19.9 ; v1(24.997,8.051) U2.17
  TOP w1: pad.2@14.22,20.9 14.22,23.65 pad.2@14.22,26.7
  SIG 1 w0.15: pad.2@14.22,20.9 14.387,20.733 14.387,20.391 16.089,18.69 19.087,18.69 19.239,18.842 19.591,18.842 19.743,18.69 20.363,18.69 22.335,16.718 22.335,9.905 24.189,8.051 27.632,8.051 27.801,8.22 29.98,8.22 30.448,7.752 31.152,7.752 32.957,9.557 32.957,13.66 v1(32.911,13.706)
  BOTTOM w0.15: ICPS2.3 31.801,13.671 32.876,13.671 v1(32.911,13.706)
SCLK_2: ICPS1.3 U1.15 | length 18.1
  TOP w0.15: U1.15@19.555,17.154 20.131,17.154 20.14,17.145 20.288,17.145 v2(20.334,17.099)
  PWR w0.15: v1(4.436,16.906) 4.749,17.219 20.023,17.219 20.096,17.145 20.288,17.145 v2(20.334,17.099)
  BOTTOM w0.15: ICPS1.3@4.453,15.717 v1@4.453,16.889
SS: J5.3 pad.2@18.03,20.9 pad.2@18.03,23.65 pad.2@18.03,26.7 U2.14 | length 22
  TOP w0.15: v2@24.968,9.744 U2.14@25.491,9.744
  TOP w1: pad.2@18.03,20.9 18.03,23.65 pad.2@18.03,26.7
  SIG 1 w0.15: pad.2@18.03,20.9 18.197,20.733 18.197,20.403 18.808,19.792 20.686,19.792 23.235,17.243 23.235,10.476 23.934,9.777 24.924,9.777 v2(24.962,9.738)
USBVCC: D2.A L1.2 U1.31 | length 5.8
  TOP w0.25: D2.A 13.598,13.635 13.794,13.831 13.794,14.281 14.163,14.65 U1.31@14.812,14.65
  TOP w0.3: L1.2 12.09,12.49 12.5,12.9 D2.A
VBUS: D1.4 J1.A4 J1.A9 J1.B4 J1.B9 L1.1 | length 15.5
  TOP w0.15: J1.A4@9.11,16.954 9.189,16.875 9.46,16.875 10.013,16.322 11.159,16.322 12.187,17.35 D1.4
  TOP w0.25: J1.B4@7.324,14.706 5.818,14.706 5.43,15.095 5.43,16.966 5.832,17.368 6.644,17.368 6.806,17.206 7.324,17.206 J1.B9 ; J1.B4@7.332,14.702 8.128,14.702 8.379,14.45 J1.A9 9.035,14.445 9.556,14.445 9.981,14.02 10.49,14.02 L1.1 ; J1.B9@7.342,17.212 7.355,17.225 7.816,17.225 7.957,17.365 8.226,17.365 8.616,16.975 9.005,16.975 J1.A4
VIN: C5.2 C14.2 J4.1 J6.1 pad.2@22.86,0 pad.2@22.86,3 pad.2@22.86,5.9 R12.2 U5.16 | length 38.4
  TOP w0.15: R12.2@5.397,5.122 5.397,4.626 5.849,4.174 C5.2@5.849,4.042
  TOP w0.25: v1(3.789,5.251) 3.818,5.222 3.818,5.099 5.243,3.674 6.124,3.674 C5.2 ; C14.2@4.475,7.525 4.646,7.696 5.328,7.696 5.681,8.05 U5.16
  TOP w0.3: v1(3.789,5.251) 4.4,5.862 C14.2
  TOP w1: pad.2@22.86,0 22.86,3 pad.2@22.86,5.9
  SIG 1 w0.5: J6.1@1.27,4.04 1.588,4.04 1.848,4.3 2.838,4.3 v1(3.789,5.251) 5.851,7.313 21.492,7.313 pad.2@22.86,5.945
pads on no net: J1.0 J1.A2 J1.A3 J1.A8 J1.A10 J1.A11 J1.B2 J1.B3 J1.B8 J1.B10 J1.B11 PB1.PAD TP_XTAL1.X U1.5 U1.6 U1.7 U1.12 U1.14 U1.18 U1.19 U1.20 U1.21 U1.22 U1.23 U1.25 U1.26 U2.19 U2.22 U5.2 U5.4 U5.5 U5.6 U5.10 U5.11 U5.15 U6.4

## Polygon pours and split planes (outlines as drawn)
no net on Bottom Solder "NONET_L-01_P-001" (solid): 16.5,11.66 16.908,11.66 17,11.568 17,10.6 16.6,10.6 16.3,10.9 16.5,11.1
no net on Bottom Solder "NONET_L-01_P-001" (solid): 16.3,11.4 16.5,11.6 16.5,11.66 16.908,11.66 16.975,11.593 16.9,11.518 16.9,10.8 16.4,10.8 16.3,10.9
GND on BOTTOM "GND_L04_P000" (solid, pour order 0): 0,26.6 34.2,26.6 34.2,0.1 0.1,0.1 0,0 0,12.4
GND on SIG 1 "NONET_L-01_P-001" (solid, remove dead copper, pour order 3): 0,0 34.2,0 34.2,26.7 0,26.7
+5V on PWR "NONET_L-01_P-001" (solid, remove dead copper, pour order 2): 0,-0.014 0.15,-0.164 33.993,-0.164 33.993,26.693 34,26.7 -0.1,26.7 0,26.6
GND on TOP "GND_L01_P001" (solid, pour order 1): 0,26.6 34.2,26.6 34.2,0.1 0.041,0.1 0,0.141 0,12.4

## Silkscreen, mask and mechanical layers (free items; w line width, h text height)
Board:
  lines w0.127: 0,0.451 0,26.2 cw(c0.5,26.2) 0.5,26.7 32.3,26.7 33,26 33,20.2 34.2,19 34.2,2.5 33,1.3 33,0.5 cw(c32.5,0.5) 32.5,0 0.5,0 cw(c0.5,0.5) 0,0.5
